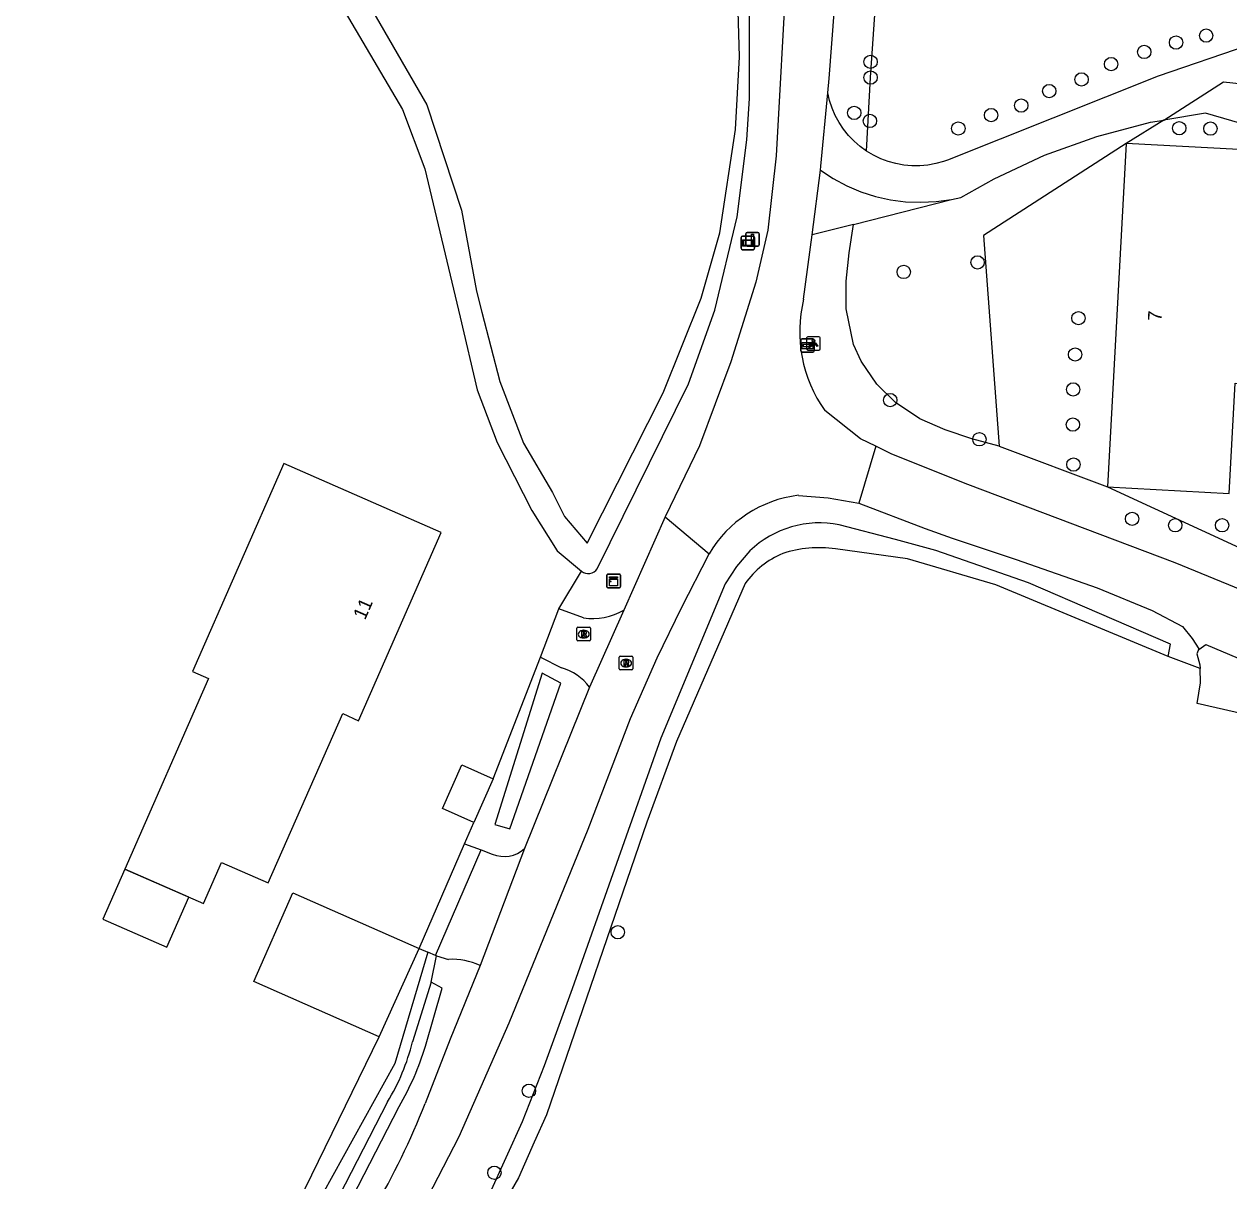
# Model space of a CAD drawing. Extents: x 163863 to 164644, y 379566 to 382155.
# Drawn here: x 164381.7 to 164470.1, y 381253.7 to 381338.5 of the extents above; entities that cross this region are included whole.
import ezdxf

# ---------------------------------------------------------------- set-up
doc = ezdxf.new("R2010")
doc.units = 0
for name, color, linetype in [('IMGEO_Boom', 7, 'Continuous'), ('IMGEO_Grasland_overig', 7, 'Continuous'), ('IMGEO_Groenvoorziening', 7, 'Continuous'), ('IMGEO_Haag', 7, 'Continuous'), ('IMGEO_Kast', 7, 'Continuous'), ('IMGEO_Lichtpunt', 7, 'Continuous'), ('IMGEO_Pand', 7, 'Continuous'), ('IMGEO_Pand_nummerreeks', 7, 'Continuous'), ('IMGEO_Pand_overbouw', 7, 'Continuous'), ('IMGEO_Rijbaan_lokaal_gesloten', 7, 'Continuous'), ('IMGEO_Rijbaan_lokaal_onverhard', 7, 'Continuous'), ('IMGEO_Rijbaan_lokaal_open', 7, 'Continuous'), ('IMGEO_Rioolput', 7, 'Continuous'), ('IMGEO_Verkeersbordpaal', 7, 'Continuous'), ('IMGEO_Verklikker', 7, 'Continuous'), ('IMGEO_Voetpad_open', 7, 'Continuous'), ('IMGEO_Waterloop', 7, 'Continuous'), ('IMGEO_Wegwijzer', 7, 'Continuous')]:
    doc.layers.add(name, color=color, linetype=linetype)

msp = doc.modelspace()

# ---------------------------------------------------------------- linework, layer by layer
at = {"layer": 'IMGEO_Boom'}
for centre in [(164468.388, 381337.632), (164466.181, 381337.123), (164463.846, 381336.431), (164443.791, 381335.711), (164461.422, 381335.541), (164443.791, 381334.557), (164459.253, 381334.417), (164456.883, 381333.568), (164454.831, 381332.506), (164442.59, 381331.967), (164452.627, 381331.808), (164443.738, 381331.377), (164450.222, 381330.825), (164466.417, 381330.842), (164468.704, 381330.815), (164451.629, 381321.013), (164446.217, 381320.312), (164459.029, 381316.926), (164458.783, 381314.264), (164458.64, 381311.705), (164445.23, 381310.921), (164458.619, 381309.125), (164451.764, 381308.047), (164458.66, 381306.197), (164462.962, 381302.22), (164466.124, 381301.745), (164469.554, 381301.745), (164425.258, 381271.924), (164418.748, 381260.307), (164416.211, 381254.302)]:
    msp.add_circle(centre, 0.489, dxfattribs=at)
at = {"layer": 'IMGEO_Grasland_overig'}
for points in [[(164478.189, 381332.234), (164476.058, 381329.711), (164468.34, 381331.955), (164465.276, 381331.438)], [(164394.859, 381239.019), (164397.405, 381243.031), (164407.776, 381264.263)]]:
    msp.add_lwpolyline(points, dxfattribs=at)
at = {"layer": 'IMGEO_Groenvoorziening'}
for points in [[(164443.503, 381329.167), (164443.791, 381334.557), (164444.186, 381340.215), (164444.308, 381342.237)], [(164465.276, 381331.438), (164462.527, 381329.731)], [(164462.527, 381329.731), (164452.067, 381322.978), (164453.209, 381307.534)], [(164442.531, 381323.8), (164449.715, 381325.625)], [(164442.531, 381323.8), (164439.498, 381323.039)], [(164453.209, 381307.534), (164451.204, 381308.088), (164449.251, 381308.732), (164447.405, 381309.557), (164445.606, 381310.742), (164444.249, 381312.082), (164443.088, 381313.781), (164442.544, 381314.984), (164442.002, 381317.607), (164441.998, 381319.634), (164442.21, 381321.705), (164442.531, 381323.8)], [(164453.209, 381307.534), (164461.167, 381304.566)], [(164461.167, 381304.566), (164478.695, 381296.475)], [(164420.949, 381295.633), (164422.604, 381298.393)], [(164416.124, 381283.158), (164419.601, 381292.089)], [(164467.944, 381291.26), (164465.612, 381292.138)], [(164414.032, 381278.407), (164414.712, 381279.968)]]:
    msp.add_lwpolyline(points, dxfattribs=at)
at = {"layer": 'IMGEO_Haag'}
for points in [[(164411.337, 381270.454), (164408.929, 381262.312), (164402.107, 381250), (164398.129, 381242.821)], [(164411.592, 381268.261), (164411.969, 381270.189)]]:
    msp.add_lwpolyline(points, dxfattribs=at)
at = {"layer": 'IMGEO_Kast'}
for p, q in [((164424.452, 381297.248), (164424.452, 381298.089)), ((164424.452, 381298.089), (164424.452, 381297.248)), ((164424.527, 381298.173), (164425.368, 381298.173)), ((164425.368, 381298.173), (164424.527, 381298.173)), ((164425.452, 381298.098), (164425.452, 381297.257)), ((164425.452, 381297.257), (164425.452, 381298.098)), ((164425.377, 381297.173), (164424.536, 381297.173)), ((164424.536, 381297.173), (164425.377, 381297.173))]:
    msp.add_line(p, q, dxfattribs=at)
for points in [[(164424.647, 381297.963), (164425.247, 381297.963), (164425.247, 381297.878), (164424.647, 381297.878), (164424.647, 381297.963)], [(164424.647, 381297.788), (164425.247, 381297.788), (164425.247, 381297.299), (164424.647, 381297.299), (164424.647, 381297.788)]]:
    msp.add_lwpolyline(points, dxfattribs=at)
msp.add_circle((164424.731, 381297.637), 0.0377, dxfattribs=at)
for centre, start, end in [((164424.53, 381298.095), 92.4484, 184.28452), ((164424.53, 381298.095), 92.4484, 184.28452), ((164425.374, 381298.095), 2.4484, 94.28452), ((164425.374, 381298.095), 2.4484, 94.28452), ((164424.53, 381297.251), 182.4484, 274.28452), ((164424.53, 381297.251), 182.4484, 274.28452), ((164425.374, 381297.251), 272.4484, 4.28452), ((164425.374, 381297.251), 272.4484, 4.28452)]:
    msp.add_arc(centre, 0.0779, start, end, dxfattribs=at)
at = {"layer": 'IMGEO_Lichtpunt'}
for p, q in [((164439.104, 381315.474), (164439.104, 381314.667)), ((164439.104, 381315.474), (164439.104, 381314.667)), ((164440.006, 381315.569), (164439.198, 381315.569)), ((164440.006, 381315.569), (164439.198, 381315.569)), ((164440.1, 381314.667), (164440.1, 381315.474)), ((164440.1, 381314.667), (164440.1, 381315.474)), ((164439.198, 381314.573), (164440.006, 381314.573)), ((164439.198, 381314.573), (164440.006, 381314.573))]:
    msp.add_line(p, q, dxfattribs=at)
for points in [[(164439.478, 381315.138), (164439.517, 381315.11), (164439.329, 381314.848), (164439.291, 381314.875), (164439.478, 381315.138)], [(164439.69, 381315.11), (164439.728, 381315.137), (164439.915, 381314.875), (164439.876, 381314.847), (164439.69, 381315.11)], [(164439.58, 381315.09), (164439.627, 381315.09), (164439.627, 381314.768), (164439.58, 381314.768), (164439.58, 381315.09)]]:
    msp.add_lwpolyline(points, dxfattribs=at)
msp.add_circle((164439.603, 381315.272), 0.0994, dxfattribs=at)
for centre, start, end in [((164439.198, 381315.474), 90, 180), ((164439.198, 381315.474), 90, 180), ((164440.006, 381315.474), 0, 90), ((164440.006, 381315.474), 0, 90), ((164439.198, 381314.667), 180, 270), ((164439.198, 381314.667), 180, 270), ((164440.006, 381314.667), 270, 0), ((164440.006, 381314.667), 270, 360)]:
    msp.add_arc(centre, 0.0946, start, end, dxfattribs=at)
at = {"layer": 'IMGEO_Pand'}
for points in [[(164461.167, 381304.566), (164470.072, 381304.084), (164470.509, 381312.16), (164473.995, 381311.972), (164474.919, 381329.061), (164462.527, 381329.731)], [(164462.527, 381329.731), (164461.167, 381304.566)], [(164412.318, 381301.219), (164407.741, 381303.229), (164400.778, 381306.287), (164394.084, 381291.043), (164395.266, 381290.525), (164389.132, 381276.554), (164394.89, 381274.028), (164396.214, 381277.046), (164399.642, 381275.541), (164405.108, 381287.946), (164406.259, 381287.405), (164412.318, 381301.219)], [(164414.712, 381279.968), (164412.407, 381281.003), (164413.837, 381284.186), (164416.124, 381283.158)], [(164416.124, 381283.158), (164414.712, 381279.968)], [(164407.776, 381264.263), (164398.58, 381268.308), (164401.439, 381274.806), (164410.692, 381270.735)], [(164407.776, 381264.263), (164410.692, 381270.735)]]:
    msp.add_lwpolyline(points, dxfattribs=at)
at = {"layer": 'IMGEO_Pand_overbouw'}
msp.add_lwpolyline([(164393.811, 381274.501), (164389.132, 381276.554), (164387.525, 381272.89), (164392.204, 381270.838)], close=True, dxfattribs=at)
at = {"layer": 'IMGEO_Rijbaan_lokaal_gesloten'}
for points in [[(164442.222, 381457.681), (164442.243, 381448.348), (164442.258, 381444.544), (164442.306, 381432.689), (164442.03, 381410.668), (164440.934, 381376.029), (164437.62, 381342.513), (164436.858, 381328.833), (164436.269, 381323.374), (164435.383, 381319.575), (164433.555, 381313.718), (164431.245, 381307.561), (164428.738, 381302.368)], [(164440.655, 381333.446), (164440.752, 381334.49), (164441.337, 381342.212), (164444.131, 381379.084)], [(164440.117, 381327.765), (164440.155, 381328.055), (164440.655, 381333.446)], [(164439.498, 381323.039), (164440.117, 381327.765)], [(164438.88, 381318.314), (164439.498, 381323.039)], [(164444.17, 381307.541), (164443.049, 381308.08), (164440.438, 381310.155)], [(164444.17, 381307.541), (164442.93, 381303.374)], [(164438.496, 381303.942), (164440.691, 381303.766), (164442.93, 381303.374)], [(164428.738, 381302.368), (164425.699, 381295.539)], [(164428.738, 381302.368), (164431.962, 381299.663)], [(164355.421, 381179.801), (164356.261, 381180.831), (164366.176, 381192.146), (164368.284, 381194.508), (164373.243, 381200.612), (164380.374, 381209.133), (164401.602, 381236.075), (164407.489, 381245.086), (164413.629, 381256.967), (164417.299, 381265.288), (164423.084, 381279.484), (164426.203, 381287.587), (164428.149, 381292.036), (164429.936, 381295.691), (164431.962, 381299.663)], [(164425.699, 381295.539), (164423.197, 381289.883)], [(164423.197, 381289.883), (164418.426, 381278.072)], [(164418.426, 381278.072), (164415.163, 381269.499)], [(164415.163, 381269.499), (164412.983, 381264.094), (164411.143, 381259.383)]]:
    msp.add_lwpolyline(points, dxfattribs=at)
for centre, radius, start, end in [((164448.537, 381315.93), 9.947, 166.13246, 215.48905), ((164439.55, 381295.205), 8.801, 96.87712, 149.56303), ((164356.131, 381281.239), 59.195, 329.96112, 338.3322)]:
    msp.add_arc(centre, radius, start, end, dxfattribs=at)
at = {"layer": 'IMGEO_Rijbaan_lokaal_onverhard'}
for points in [[(164510.588, 381341.959), (164510.298, 381341.836), (164509.802, 381341.668), (164509.294, 381341.544), (164508.776, 381341.467), (164508.254, 381341.435), (164507.731, 381341.451), (164500, 381340.973), (164487.327, 381340.189), (164479.318, 381338.909), (164471.455, 381336.919), (164464.882, 381334.661), (164449.427, 381328.515), (164449.128, 381328.41), (164448.562, 381328.254), (164447.985, 381328.149), (164447.4, 381328.097), (164446.814, 381328.097), (164446.229, 381328.149), (164445.652, 381328.253), (164445.086, 381328.408), (164444.537, 381328.613), (164444.007, 381328.867), (164443.503, 381329.167)], [(164465.276, 381331.438), (164469.657, 381334.244), (164477.814, 381333.353)], [(164443.503, 381329.167), (164443.028, 381329.51), (164442.585, 381329.895), (164442.178, 381330.318), (164441.811, 381330.775), (164441.485, 381331.264), (164441.205, 381331.779), (164440.972, 381332.318), (164440.788, 381332.875), (164440.655, 381333.446)], [(164449.715, 381325.625), (164450.405, 381325.773), (164452.845, 381327.14), (164456.541, 381328.86), (164460.376, 381330.243), (164464.32, 381331.277), (164465.276, 381331.438)], [(164440.117, 381327.765), (164441.058, 381327.153), (164442.049, 381326.627), (164443.084, 381326.191), (164444.153, 381325.85), (164445.248, 381325.606), (164446.361, 381325.461), (164447.483, 381325.415), (164448.604, 381325.47), (164449.715, 381325.625)], [(164532.041, 381277.331), (164528.232, 381278.11), (164521.819, 381279.707), (164508.891, 381283.704), (164495.223, 381288.05), (164486.159, 381290.941), (164477.26, 381294.425), (164466.11, 381299.002), (164450.929, 381304.74), (164445.359, 381306.969), (164444.17, 381307.541)], [(164442.93, 381303.374), (164447.793, 381301.508), (164449.776, 381300.806), (164454.459, 381299.235), (164460.4, 381297.168), (164464.441, 381295.494), (164466.649, 381294.342), (164467.37, 381293.461), (164467.841, 381292.683)]]:
    msp.add_lwpolyline(points, dxfattribs=at)
at = {"layer": 'IMGEO_Rijbaan_lokaal_open'}
for points in [[(164467.841, 381292.683), (164467.716, 381292.319), (164467.936, 381291.524), (164467.944, 381291.26)], [(164467.841, 381292.683), (164467.86, 381292.651), (164468.367, 381293.007), (164474.215, 381290.55)], [(164473.355, 381289.222), (164473.052, 381288.89), (164472.767, 381287.543), (164467.729, 381288.691), (164467.974, 381290.201), (164467.944, 381291.26)]]:
    msp.add_lwpolyline(points, dxfattribs=at)
at = {"layer": 'IMGEO_Rioolput'}
for p, q in [((164422.265, 381293.345), (164422.265, 381294.197)), ((164422.34, 381294.271), (164423.192, 381294.271)), ((164422.753, 381294.051), (164422.778, 381294.051)), ((164423.266, 381294.197), (164423.266, 381293.345)), ((164423.192, 381293.271), (164422.34, 381293.271)), ((164422.776, 381293.491), (164422.751, 381293.491)), ((164425.371, 381291.219), (164425.371, 381292.071)), ((164425.446, 381292.145), (164426.298, 381292.145)), ((164425.882, 381291.365), (164425.857, 381291.365)), ((164425.859, 381291.925), (164425.884, 381291.925)), ((164426.372, 381292.071), (164426.372, 381291.219)), ((164426.298, 381291.145), (164425.446, 381291.145))]:
    msp.add_line(p, q, dxfattribs=at)
for points in [[(164422.265, 381293.345), (164422.265, 381294.197)], [(164422.34, 381294.271), (164423.192, 381294.271)], [(164422.854, 381293.969), (164422.602, 381293.971), (164422.602, 381293.571)], [(164423.266, 381294.197), (164423.266, 381293.345)], [(164423.192, 381293.271), (164422.34, 381293.271)], [(164422.602, 381293.571), (164422.726, 381293.571), (164422.726, 381293.733), (164422.737, 381293.733)], [(164422.78, 381293.89), (164422.726, 381293.89), (164422.726, 381293.809)], [(164422.726, 381293.809), (164422.778, 381293.809)], [(164422.784, 381293.704), (164422.855, 381293.571), (164422.995, 381293.571), (164422.93, 381293.697)], [(164425.371, 381291.219), (164425.371, 381292.071)], [(164425.446, 381292.145), (164426.298, 381292.145)], [(164425.96, 381291.843), (164425.708, 381291.845), (164425.708, 381291.445)], [(164425.708, 381291.445), (164425.832, 381291.445), (164425.832, 381291.607), (164425.843, 381291.607)], [(164425.886, 381291.764), (164425.832, 381291.764), (164425.832, 381291.683)], [(164425.832, 381291.683), (164425.884, 381291.683)], [(164425.89, 381291.578), (164425.961, 381291.445), (164426.101, 381291.445), (164426.036, 381291.571)], [(164426.372, 381292.071), (164426.372, 381291.219)], [(164426.298, 381291.145), (164425.446, 381291.145)]]:
    msp.add_lwpolyline(points, dxfattribs=at)
for centre, radius, start, end in [((164422.342, 381294.195), 0.0765, 91.55205, 178.44795), ((164422.342, 381294.195), 0.0765, 91.55205, 178.44795), ((164422.853, 381293.859), 0.109, 350.36119, 89.41601), ((164423.19, 381294.195), 0.0765, 1.55205, 88.44795), ((164423.19, 381294.195), 0.0765, 1.55205, 88.44795), ((164422.342, 381293.347), 0.0765, 181.55205, 268.44795), ((164422.342, 381293.347), 0.0765, 181.55205, 268.44795), ((164422.736, 381293.68), 0.0533, 26.02933, 88.69889), ((164422.762, 381293.998), 0.19, 274.7715, 282.96867), ((164422.786, 381293.794), 0.0964, 77.00612, 93.18647), ((164422.8, 381293.851), 0.0378, 276.66336, 79.67722), ((164422.851, 381293.859), 0.112, 277.58423, 350.98172), ((164422.835, 381293.644), 0.108, 29.51342, 73.79051), ((164423.19, 381293.347), 0.0765, 271.55205, 358.44795), ((164423.19, 381293.347), 0.0765, 271.55205, 358.44795), ((164425.448, 381292.069), 0.0765, 91.55205, 178.44795), ((164425.448, 381292.069), 0.0765, 91.55205, 178.44795), ((164425.842, 381291.554), 0.0533, 26.02933, 88.69889), ((164425.868, 381291.872), 0.19, 274.7715, 282.96867), ((164425.892, 381291.668), 0.0964, 77.00612, 93.18647), ((164425.906, 381291.725), 0.0378, 276.66336, 79.67722), ((164425.959, 381291.733), 0.109, 350.36119, 89.41601), ((164425.957, 381291.733), 0.112, 277.58423, 350.98172), ((164425.941, 381291.518), 0.108, 29.51342, 73.79051), ((164426.296, 381292.069), 0.0765, 1.55205, 88.44795), ((164426.296, 381292.069), 0.0765, 1.55205, 88.44795), ((164425.448, 381291.221), 0.0765, 181.55205, 268.44795), ((164425.448, 381291.221), 0.0765, 181.55205, 268.44795), ((164426.296, 381291.221), 0.0765, 271.55205, 358.44795), ((164426.296, 381291.221), 0.0765, 271.55205, 358.44795)]:
    msp.add_arc(centre, radius, start, end, dxfattribs=at)
for centre, major_axis, ratio, start_param, end_param in [((164422.752, 381293.771), (-0.387, 0.002), 0.722429, 4.712389, 7.853982), ((164422.777, 381293.771), (-0.39, 0.002), 0.717154, 1.570796, 4.712389), ((164425.858, 381291.645), (-0.387, 0.002), 0.722429, 4.712389, 7.853982), ((164425.883, 381291.645), (-0.39, 0.002), 0.717154, 1.570796, 4.712389)]:
    msp.add_ellipse(centre, major_axis=major_axis, ratio=ratio, start_param=start_param, end_param=end_param, dxfattribs=at)
at = {"layer": 'IMGEO_Verkeersbordpaal'}
for p, q in [((164434.634, 381322.299), (164434.634, 381323.099)), ((164434.634, 381323.099), (164434.634, 381322.299)), ((164434.734, 381323.199), (164435.524, 381323.199)), ((164435.524, 381323.199), (164434.734, 381323.199)), ((164435.624, 381323.099), (164435.624, 381322.299)), ((164435.624, 381322.299), (164435.624, 381323.099)), ((164435.524, 381322.199), (164434.734, 381322.199)), ((164434.734, 381322.199), (164435.524, 381322.199))]:
    msp.add_line(p, q, dxfattribs=at)
msp.add_lwpolyline([(164435.054, 381323.074), (164435.204, 381323.074), (164435.204, 381322.324), (164435.054, 381322.324), (164435.054, 381323.074)], dxfattribs=at)
for centre, start, end in [((164434.734, 381323.099), 90, 180), ((164434.734, 381323.099), 90, 180), ((164435.524, 381323.099), 0, 90), ((164435.524, 381323.099), 360, 90), ((164434.734, 381322.299), 180, 270), ((164434.734, 381322.299), 180, 270), ((164435.524, 381322.299), 270, 0), ((164435.524, 381322.299), 270, 0)]:
    msp.add_arc(centre, 0.1, start, end, dxfattribs=at)
at = {"layer": 'IMGEO_Verklikker'}
for p, q in [((164434.301, 381322.044), (164434.301, 381322.844)), ((164434.301, 381322.844), (164434.301, 381322.044)), ((164434.401, 381322.944), (164435.191, 381322.944)), ((164435.191, 381322.944), (164434.401, 381322.944)), ((164435.291, 381322.844), (164435.291, 381322.044)), ((164435.291, 381322.044), (164435.291, 381322.844)), ((164435.191, 381321.944), (164434.401, 381321.944)), ((164434.401, 381321.944), (164435.191, 381321.944))]:
    msp.add_line(p, q, dxfattribs=at)
for points in [[(164434.402, 381322.676), (164435.19, 381322.676), (164435.19, 381322.212), (164434.402, 381322.212), (164434.402, 381322.676)], [(164434.467, 381322.611), (164434.467, 381322.277), (164435.125, 381322.277), (164435.125, 381322.611), (164434.467, 381322.611)]]:
    msp.add_lwpolyline(points, dxfattribs=at)
for centre, start, end in [((164434.401, 381322.844), 90, 180), ((164434.401, 381322.844), 90, 180), ((164435.191, 381322.844), 0, 90), ((164435.191, 381322.844), 360, 90), ((164434.401, 381322.044), 180, 270), ((164434.401, 381322.044), 180, 270), ((164435.191, 381322.044), 270, 0), ((164435.191, 381322.044), 270, 0)]:
    msp.add_arc(centre, 0.1, start, end, dxfattribs=at)
at = {"layer": 'IMGEO_Voetpad_open'}
for points in [[(164419.601, 381292.089), (164420.949, 381295.633)], [(164422.744, 381294.97), (164420.949, 381295.633)], [(164419.601, 381292.089), (164421.124, 381291.309)], [(164410.692, 381270.735), (164414.032, 381278.407)], [(164414.032, 381278.407), (164415.235, 381277.962)], [(164411.898, 381270.209), (164415.235, 381277.962)], [(164415.235, 381277.962), (164416.06, 381277.657)], [(164410.692, 381270.735), (164411.337, 381270.454)], [(164411.898, 381270.209), (164411.337, 381270.454)], [(164411.969, 381270.189), (164411.898, 381270.209)], [(164411.969, 381270.189), (164412.86, 381269.935)]]:
    msp.add_lwpolyline(points, dxfattribs=at)
for centre, radius, start, end in [((164423.459, 381299.216), 4.306, 260.44736, 301.35102), ((164420.058, 381287.539), 3.918, 36.74639, 74.20607), ((164416.931, 381279.643), 2.168, 246.31472, 313.58241), ((164413.108, 381264.943), 4.998, 65.71779, 92.84168)]:
    msp.add_arc(centre, radius, start, end, dxfattribs=at)
at = {"layer": 'IMGEO_Waterloop'}
for points in [[(164423.745, 381298.566), (164430.454, 381312.123), (164432.381, 381317.5), (164434.012, 381324.358), (164434.72, 381329.997), (164434.906, 381333.017), (164434.917, 381340.077), (164434.377, 381351.459), (164434.484, 381356.019), (164434.81, 381360.278), (164438.006, 381382.933), (164438.494, 381387.993), (164438.663, 381393.573), (164438.58, 381403.854), (164438.226, 381407.474), (164437.474, 381412.376), (164437.16, 381415.957), (164437.215, 381424.457), (164437.58, 381427.897), (164436.26, 381427.879)], [(164387.166, 381367.345), (164390.157, 381362.394), (164393.805, 381357.162), (164399.948, 381348.42), (164409.49, 381332.219), (164411.116, 381327.859), (164413.703, 381316.994), (164414.964, 381311.676), (164416.411, 381307.805), (164418.968, 381302.834), (164420.828, 381299.875), (164422.604, 381298.393)], [(164401.574, 381349.362), (164411.254, 381332.57), (164413.803, 381324.847), (164414.912, 381318.899), (164415.306, 381317.364), (164416.618, 381312.275), (164418.341, 381307.767), (164420.475, 381304.145), (164421.353, 381302.387), (164423.018, 381300.443), (164428.593, 381311.446), (164431.363, 381318.402), (164432.75, 381323.18), (164433.882, 381330.758), (164434.191, 381336.078), (164433.566, 381357.04)], [(164465.612, 381292.138), (164465.778, 381293.037), (164455.369, 381297.524), (164448.566, 381299.888), (164445.628, 381300.717), (164441.495, 381301.788)], [(164434.95, 381299.874), (164433.959, 381298.733), (164433.135, 381297.466), (164428.425, 381286.135), (164421.914, 381267.784), (164419.865, 381262.136), (164418.248, 381258.03), (164415.85, 381252.761), (164414.21, 381250.168), (164412.866, 381247.752), (164408.093, 381239.754)], [(164465.612, 381292.138), (164452.976, 381297.383), (164446.503, 381299.301), (164441.209, 381300.014)], [(164434.594, 381297.476), (164429.564, 381285.908), (164427.387, 381279.981), (164420.028, 381258.538), (164419.12, 381256.54), (164417.976, 381253.924), (164415.715, 381250), (164411.163, 381242.333), (164409.255, 381239.259)], [(164417.335, 381279.508), (164421.076, 381290.167), (164419.715, 381290.907), (164416.246, 381279.823), (164417.335, 381279.508)], [(164411.592, 381268.261), (164410.209, 381263.894)], [(164411.162, 381263.577), (164412.389, 381267.831), (164411.592, 381268.261)], [(164398.129, 381242.821), (164396.982, 381242.283), (164397.166, 381241.124), (164401.041, 381243.212), (164404.527, 381250), (164409.232, 381259.161)], [(164408.372, 381259.485), (164403.482, 381250), (164400.313, 381243.854), (164398.129, 381242.821)]]:
    msp.add_lwpolyline(points, dxfattribs=at)
for centre, radius, start, end in [((164440.073, 381294.503), 7.422, 78.955, 133.64674), ((164439.857, 381293.72), 6.465, 112.82995, 144.4846), ((164439.999, 381291.545), 8.555, 81.86677, 108.05094), ((164423.103, 381298.949), 0.747, 228.05898, 329.18421), ((164395.447, 381267.457), 15.186, 328.33305, 346.42906), ((164391.521, 381269.531), 20.524, 329.64991, 343.1349)]:
    msp.add_arc(centre, radius, start, end, dxfattribs=at)
at = {"layer": 'IMGEO_Wegwijzer'}
for p, q in [((164438.676, 381314.522), (164438.676, 381315.322)), ((164438.676, 381315.322), (164438.676, 381314.522)), ((164438.776, 381315.422), (164439.566, 381315.422)), ((164439.566, 381315.422), (164438.776, 381315.422)), ((164439.666, 381315.322), (164439.666, 381314.522)), ((164439.666, 381314.522), (164439.666, 381315.322)), ((164439.566, 381314.422), (164438.776, 381314.422)), ((164438.776, 381314.422), (164439.566, 381314.422))]:
    msp.add_line(p, q, dxfattribs=at)
for points in [[(164438.777, 381315.154), (164439.565, 381315.154), (164439.565, 381314.69), (164438.777, 381314.69), (164438.777, 381315.154)], [(164438.842, 381315.006), (164438.842, 381314.922), (164438.842, 381314.838), (164439.253, 381314.838), (164439.253, 381314.755), (164439.5, 381314.922), (164439.253, 381315.089), (164439.253, 381315.006), (164438.842, 381315.006)]]:
    msp.add_lwpolyline(points, dxfattribs=at)
for centre, start, end in [((164438.776, 381315.322), 90, 180), ((164438.776, 381315.322), 90, 180), ((164439.566, 381315.322), 0, 90), ((164439.566, 381315.322), 360, 90), ((164438.776, 381314.522), 180, 270), ((164438.776, 381314.522), 180, 270), ((164439.566, 381314.522), 270, 0), ((164439.566, 381314.522), 270, 0)]:
    msp.add_arc(centre, 0.1, start, end, dxfattribs=at)

# ---------------------------------------------------------------- texts
at = {"layer": 'IMGEO_Pand_nummerreeks'}
for s, rotation, p in [('7', 86.90656, (164465.108, 381316.697)), ('11', 66.31986, (164406.732, 381294.755))]:
    msp.add_text(s, height=1, rotation=rotation, dxfattribs=at).set_placement(p)

doc.saveas('drawing.dxf')
